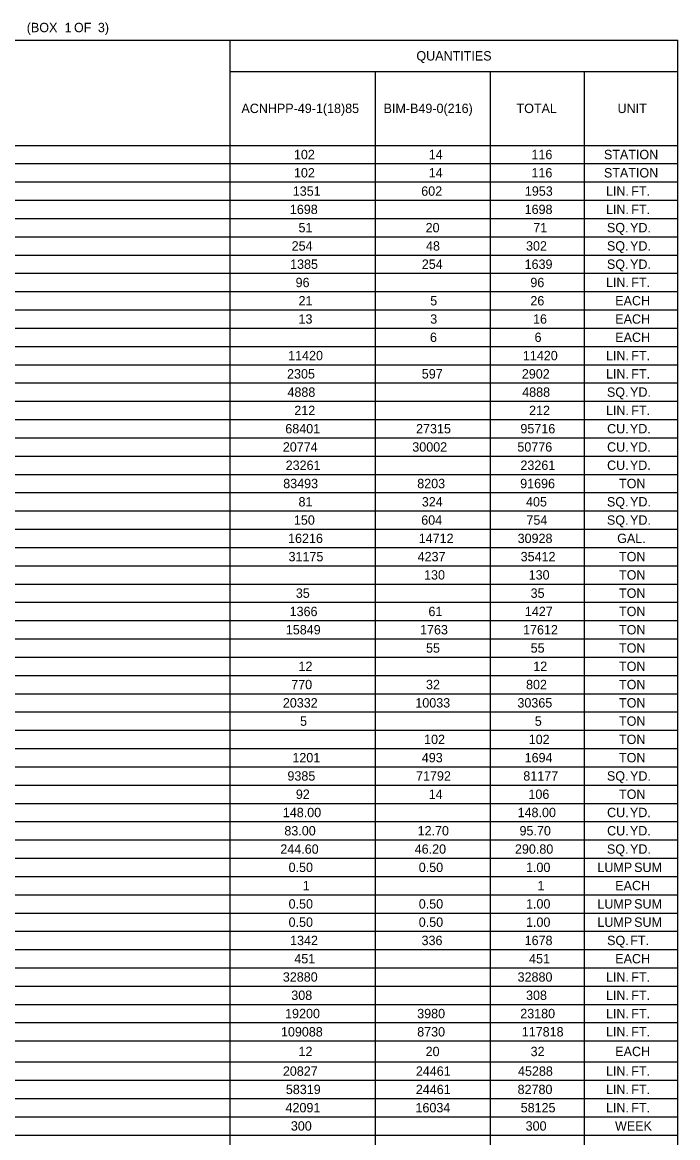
# Model space of a CAD drawing. Extents: x 1226603 to 1228117, y 151305 to 152343.
# Drawn here: x 1226938 to 1227236, y 151837 to 152343 of the extents above; entities that cross this region are included whole.
import ezdxf

# ---------------------------------------------------------------- set-up
doc = ezdxf.new("R2010")
doc.units = 0
doc.layers.add('R_Dimension', color=7, linetype='Continuous')

msp = doc.modelspace()

# ---------------------------------------------------------------- linework, layer by layer
at = {"layer": 'R_Dimension'}
for p, q in [((1226605.78, 152334.72), (1227235.63, 152334.72)), ((1227032.58, 151338.98), (1227032.58, 152334.72)), ((1227235.63, 151338.98), (1227235.63, 152334.72)), ((1227032.58, 152320.63), (1227235.63, 152320.63)), ((1227098.47, 151338.98), (1227098.47, 152320.63)), ((1227150.68, 151338.98), (1227150.68, 152320.63)), ((1227193.36, 151338.98), (1227193.36, 152320.63)), ((1226605.78, 152287.07), (1227235.63, 152287.07)), ((1226605.78, 152278.78), (1227235.63, 152278.78)), ((1226605.78, 152270.49), (1227235.63, 152270.49)), ((1226605.78, 152262.2), (1227235.63, 152262.2)), ((1226605.78, 152253.92), (1227235.63, 152253.92)), ((1226605.78, 152245.63), (1227235.63, 152245.63)), ((1226605.78, 152237.34), (1227235.63, 152237.34)), ((1226605.78, 152229.05), (1227235.63, 152229.05)), ((1226605.78, 152220.77), (1227235.63, 152220.77)), ((1226605.78, 152212.48), (1227235.63, 152212.48)), ((1226605.78, 152204.19), (1227235.63, 152204.19)), ((1226605.78, 152195.9), (1227235.63, 152195.9)), ((1226605.78, 152187.62), (1227235.63, 152187.62)), ((1226605.78, 152179.33), (1227235.63, 152179.33)), ((1226605.78, 152171.04), (1227235.63, 152171.04)), ((1226605.78, 152162.75), (1227235.63, 152162.75)), ((1226605.78, 152154.47), (1227235.63, 152154.47)), ((1226605.78, 152146.18), (1227235.63, 152146.18)), ((1226605.78, 152137.89), (1227235.63, 152137.89)), ((1226605.78, 152129.6), (1227235.63, 152129.6)), ((1226605.78, 152121.32), (1227235.63, 152121.32)), ((1226605.78, 152113.03), (1227235.63, 152113.03)), ((1226605.78, 152104.74), (1227235.63, 152104.74)), ((1226605.78, 152096.45), (1227235.63, 152096.45)), ((1226605.78, 152088.17), (1227235.63, 152088.17)), ((1226605.78, 152079.88), (1227235.63, 152079.88)), ((1226605.78, 152071.59), (1227235.63, 152071.59)), ((1226605.78, 152063.3), (1227235.63, 152063.3)), ((1226605.78, 152055.02), (1227235.63, 152055.02)), ((1226605.78, 152046.73), (1227235.63, 152046.73)), ((1226605.78, 152038.44), (1227235.63, 152038.44)), ((1226605.78, 152030.15), (1227235.63, 152030.15)), ((1226605.78, 152021.87), (1227235.63, 152021.87)), ((1226605.78, 152013.58), (1227235.63, 152013.58)), ((1226605.78, 152005.29), (1227235.63, 152005.29)), ((1226605.78, 151997), (1227235.63, 151997)), ((1226605.78, 151988.72), (1227235.63, 151988.72)), ((1226605.78, 151980.43), (1227235.63, 151980.43)), ((1226605.78, 151972.14), (1227235.63, 151972.14)), ((1226605.78, 151963.85), (1227235.63, 151963.85)), ((1226605.78, 151955.57), (1227235.63, 151955.57)), ((1226605.78, 151947.28), (1227235.63, 151947.28)), ((1226605.78, 151938.99), (1227235.63, 151938.99)), ((1226605.78, 151930.7), (1227235.63, 151930.7)), ((1226605.78, 151922.42), (1227235.63, 151922.42)), ((1226605.78, 151914.13), (1227235.63, 151914.13)), ((1226605.78, 151905.84), (1227235.63, 151905.84)), ((1226605.78, 151897.55), (1227235.63, 151897.55)), ((1226605.78, 151889.27), (1227235.63, 151889.27)), ((1226605.78, 151880.98), (1227235.63, 151880.98)), ((1226605.78, 151871.45), (1227235.63, 151871.45)), ((1226605.78, 151863.16), (1227235.63, 151863.16)), ((1226605.78, 151854.87), (1227235.63, 151854.87)), ((1226605.78, 151846.58), (1227235.63, 151846.58)), ((1226605.78, 151838.3), (1227235.63, 151838.3))]:
    msp.add_line(p, q, dxfattribs=at)

# ---------------------------------------------------------------- texts
for s, p in [(' (BOX', (1226938.77, 152338.39)), (' 1', (1226955.94, 152338.39)), (' OF', (1226960.19, 152338.39)), (' 3)', (1226971.03, 152338.39)), ('QUANTITIES', (1227117.1, 152325.55)), ('ACNHPP-49-1(18)85', (1227037.72, 152301.72)), ('BIM-B49-0(216)', (1227102.22, 152301.72)), ('TOTAL', (1227162.52, 152301.72)), ('UNIT', (1227208.35, 152301.72)), ('102', (1227061.54, 152280.8)), ('14', (1227122.67, 152280.8)), ('116', (1227169.29, 152280.8)), ('STATION', (1227202.16, 152280.8)), ('102', (1227061.54, 152272.51)), ('14', (1227122.67, 152272.51)), ('116', (1227169.29, 152272.51)), ('STATION', (1227202.16, 152272.51)), ('1351', (1227061.01, 152264.22)), ('602', (1227119.29, 152264.22)), ('1953', (1227166.3, 152264.22)), ('LIN.', (1227203.1, 152264.22)), (' FT.', (1227213, 152264.22)), ('1698', (1227059.7, 152255.93)), ('1698', (1227166.2, 152255.93)), ('LIN.', (1227203.1, 152255.93)), (' FT.', (1227213, 152255.93)), ('51', (1227063.62, 152247.65)), ('20', (1227121.28, 152247.65)), ('71', (1227170.11, 152247.65)), ('SQ.', (1227203.53, 152247.65)), (' YD.', (1227212.44, 152247.65)), ('254', (1227060.51, 152239.36)), ('48', (1227121.46, 152239.36)), ('302', (1227166.83, 152239.36)), ('SQ.', (1227203.53, 152239.36)), (' YD.', (1227212.44, 152239.36)), ('1385', (1227059.8, 152231.07)), ('254', (1227119.55, 152231.07)), ('1639', (1227166.18, 152231.07)), ('SQ.', (1227203.53, 152231.07)), (' YD.', (1227212.44, 152231.07)), ('96', (1227062.3, 152222.78)), ('96', (1227168.79, 152222.78)), ('LIN.', (1227203.1, 152222.78)), (' FT.', (1227213, 152222.78)), ('21', (1227063.62, 152214.5)), ('5', (1227123.37, 152214.5)), ('26', (1227168.79, 152214.5)), ('EACH', (1227207.3, 152214.5)), ('13', (1227063.62, 152206.21)), ('3', (1227123.37, 152206.21)), ('16', (1227170, 152206.21)), ('EACH', (1227207.3, 152206.21)), ('6', (1227123.25, 152197.92)), ('6', (1227170.7, 152197.92)), ('EACH', (1227207.3, 152197.92)), ('11420', (1227058.92, 152189.63)), ('11420', (1227165.41, 152189.63)), ('LIN.', (1227203.1, 152189.63)), (' FT.', (1227213, 152189.63)), ('2305', (1227058.43, 152181.35)), ('597', (1227119.55, 152181.35)), ('2902', (1227164.93, 152181.35)), ('LIN.', (1227203.1, 152181.35)), (' FT.', (1227213, 152181.35)), ('4888', (1227058.6, 152173.06)), ('4888', (1227165.09, 152173.06)), ('SQ.', (1227203.53, 152173.06)), (' YD.', (1227212.44, 152173.06)), ('212', (1227061.71, 152164.77)), ('212', (1227168.21, 152164.77)), ('LIN.', (1227203.1, 152164.77)), (' FT.', (1227213, 152164.77)), ('68401', (1227057.63, 152156.48)), ('27315', (1227116.94, 152156.48)), ('95716', (1227164.27, 152156.48)), ('CU.', (1227203.6, 152156.48)), (' YD.', (1227212.37, 152156.48)), ('20774', (1227056.52, 152148.2)), ('30002', (1227115.24, 152148.2)), ('50776', (1227162.9, 152148.2)), ('CU.', (1227203.6, 152148.2)), (' YD.', (1227212.37, 152148.2)), ('23261', (1227057.8, 152139.91)), ('23261', (1227164.29, 152139.91)), ('CU.', (1227203.6, 152139.91)), (' YD.', (1227212.37, 152139.91)), ('83493', (1227056.69, 152131.62)), ('8203', (1227117.48, 152131.62)), ('91696', (1227164.17, 152131.62)), ('TON', (1227209.02, 152131.62)), ('81', (1227063.62, 152123.33)), ('324', (1227119.55, 152123.33)), ('405', (1227166.83, 152123.33)), ('SQ.', (1227203.53, 152123.33)), (' YD.', (1227212.44, 152123.33)), ('150', (1227061.53, 152115.05)), ('604', (1227119.29, 152115.05)), ('754', (1227167, 152115.05)), ('SQ.', (1227203.53, 152115.05)), (' YD.', (1227212.44, 152115.05)), ('16216', (1227058.88, 152106.76)), ('14712', (1227118.15, 152106.76)), ('30928', (1227163.02, 152106.76)), ('GAL.', (1227208.17, 152106.76)), ('31175', (1227059.1, 152098.47)), ('4237', (1227117.65, 152098.47)), ('35412', (1227164.39, 152098.47)), ('TON', (1227209.02, 152098.47)), ('130', (1227120.58, 152090.18)), ('130', (1227168.02, 152090.18)), ('TON', (1227209.02, 152090.18)), ('35', (1227062.41, 152081.9)), ('35', (1227168.91, 152081.9)), ('TON', (1227209.02, 152081.9)), ('1366', (1227059.59, 152073.61)), ('61', (1227122.57, 152073.61)), ('1427', (1227166.3, 152073.61)), ('TON', (1227209.02, 152073.61)), ('15849', (1227057.88, 152065.32)), ('1763', (1227118.75, 152065.32)), ('17612', (1227165.49, 152065.32)), ('TON', (1227209.02, 152065.32)), ('55', (1227121.46, 152057.03)), ('55', (1227168.91, 152057.03)), ('TON', (1227209.02, 152057.03)), ('12', (1227063.62, 152048.75)), ('12', (1227170.11, 152048.75)), ('TON', (1227209.02, 152048.75)), ('770', (1227060.32, 152040.46)), ('32', (1227121.46, 152040.46)), ('802', (1227166.83, 152040.46)), ('TON', (1227209.02, 152040.46)), ('20332', (1227056.52, 152032.17)), ('10033', (1227116.61, 152032.17)), ('30365', (1227162.92, 152032.17)), ('TON', (1227209.02, 152032.17)), ('5', (1227064.32, 152023.88)), ('5', (1227170.82, 152023.88)), ('TON', (1227209.02, 152023.88)), ('102', (1227120.59, 152015.6)), ('102', (1227168.04, 152015.6)), ('TON', (1227209.02, 152015.6)), ('1201', (1227060.84, 152007.31)), ('493', (1227119.55, 152007.31)), ('1694', (1227166.2, 152007.31)), ('TON', (1227209.02, 152007.31)), ('9385', (1227058.6, 151999.02)), ('71792', (1227116.94, 151999.02)), ('81177', (1227165.6, 151999.02)), ('SQ.', (1227203.53, 151999.02)), (' YD.', (1227212.44, 151999.02)), ('92', (1227062.41, 151990.73)), ('14', (1227122.67, 151990.73)), ('106', (1227167.92, 151990.73)), ('TON', (1227209.02, 151990.73)), ('148.00', (1227056.51, 151982.45)), ('148.00', (1227163, 151982.45)), ('CU.', (1227203.6, 151982.45)), (' YD.', (1227212.37, 151982.45)), ('83.00', (1227057.21, 151974.16)), ('12.70', (1227117.63, 151974.16)), ('95.70', (1227163.87, 151974.16)), ('CU.', (1227203.6, 151974.16)), (' YD.', (1227212.37, 151974.16)), ('244.60', (1227055.37, 151965.87)), ('46.20', (1227116.33, 151965.87)), ('290.80', (1227161.8, 151965.87)), ('SQ.', (1227203.53, 151965.87)), (' YD.', (1227212.44, 151965.87)), ('0.50', (1227059.12, 151957.58)), ('0.50', (1227118.17, 151957.58)), ('1.00', (1227166.82, 151957.58)), ('LUMP', (1227199.2, 151957.58)), (' SUM', (1227214.29, 151957.58)), ('1', (1227065.53, 151949.3)), ('1', (1227172.02, 151949.3)), ('EACH', (1227207.3, 151949.3)), ('0.50', (1227059.12, 151941.01)), ('0.50', (1227118.17, 151941.01)), ('1.00', (1227166.82, 151941.01)), ('LUMP', (1227199.2, 151941.01)), (' SUM', (1227214.29, 151941.01)), ('0.50', (1227059.12, 151932.72)), ('0.50', (1227118.17, 151932.72)), ('1.00', (1227166.82, 151932.72)), ('LUMP', (1227199.2, 151932.72)), (' SUM', (1227214.29, 151932.72)), ('1342', (1227059.8, 151924.43)), ('336', (1227119.44, 151924.43)), ('1678', (1227166.2, 151924.43)), ('SQ.', (1227203.6, 151924.43)), (' FT.', (1227212.5, 151924.43)), ('451', (1227061.71, 151916.15)), ('451', (1227168.21, 151916.15)), ('EACH', (1227207.3, 151916.15)), ('32880', (1227056.51, 151907.86)), ('32880', (1227163, 151907.86)), ('LIN.', (1227203.1, 151907.86)), (' FT.', (1227213, 151907.86)), ('308', (1227060.34, 151899.57)), ('308', (1227166.83, 151899.57)), ('LIN.', (1227203.1, 151899.57)), (' FT.', (1227213, 151899.57)), ('19200', (1227057.54, 151891.28)), ('3980', (1227117.46, 151891.28)), ('23180', (1227164.21, 151891.28)), ('LIN.', (1227203.1, 151891.28)), (' FT.', (1227213, 151891.28)), ('109088', (1227055.65, 151883)), ('8730', (1227117.46, 151883)), ('117818', (1227164.89, 151883)), ('LIN.', (1227203.1, 151883)), (' FT.', (1227213, 151883)), ('12', (1227063.62, 151874.09)), ('20', (1227121.28, 151874.09)), ('32', (1227168.91, 151874.09)), ('EACH', (1227207.3, 151874.09)), ('20827', (1227056.52, 151865.18)), ('24461', (1227116.84, 151865.18)), ('45288', (1227163.19, 151865.18)), ('LIN.', (1227203.1, 151865.18)), (' FT.', (1227213, 151865.18)), ('58319', (1227057.88, 151856.89)), ('24461', (1227116.84, 151856.89)), ('82780', (1227163, 151856.89)), ('LIN.', (1227203.1, 151856.89)), (' FT.', (1227213, 151856.89)), ('42091', (1227057.73, 151848.6)), ('16034', (1227116.68, 151848.6)), ('58125', (1227164.39, 151848.6)), ('LIN.', (1227203.1, 151848.6)), (' FT.', (1227213, 151848.6)), ('300', (1227060.15, 151840.32)), ('300', (1227166.65, 151840.32)), ('WEEK', (1227207.2, 151840.32))]:
    msp.add_text(s, height=4.25, dxfattribs=at).set_placement(p)

doc.saveas('drawing.dxf')
